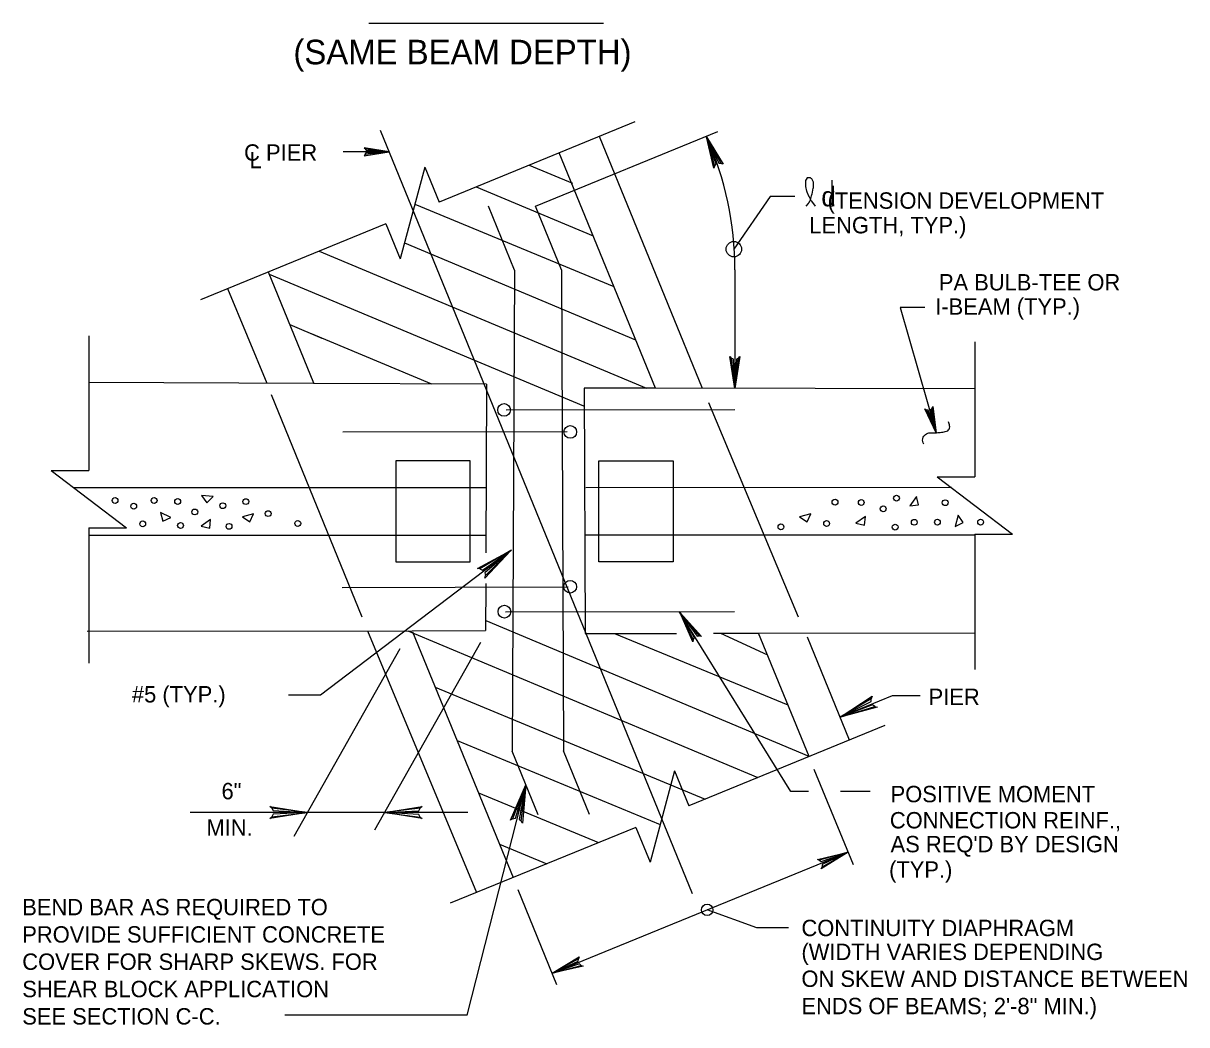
# Model space of a CAD drawing. Extents: x 639980 to 641204, y 298038 to 300414.
# Drawn here: x 640298.4 to 640511.2, y 299434.1 to 299617.3 of the extents above; entities that cross this region are included whole.
import ezdxf

# ---------------------------------------------------------------- set-up
doc = ezdxf.new("R2010")
doc.units = 0
for name, color, linetype in [('1', 7, 'Continuous'), ('2', 7, 'Continuous'), ('3', 7, 'Continuous')]:
    doc.layers.add(name, color=color, linetype=linetype)

msp = doc.modelspace()

# ---------------------------------------------------------------- linework, layer by layer
at = {"layer": '1'}
msp.add_spline([(640463.14, 299540.3), (640462.94, 299541.25), (640463.27, 299541.89), (640464.09, 299542.35), (640464.99, 299542.34), (640465.92, 299542.42), (640466.84, 299542.53), (640467.69, 299542.89), (640467.87, 299543.65), (640467.67, 299544.35)], degree=3, dxfattribs=at)
at = {"layer": '2'}
for p, q in [((640361.59, 299617.3), (640404.52, 299617.3)), ((640410.3, 299599.24), (640374.46, 299584.58)), ((640420.86, 299458.03), (640363.74, 299597.7)), ((640392.12, 299583.84), (640425.48, 299597.49)), ((640422.68, 299550.5), (640403.83, 299596.59)), ((640365.33, 299593.8), (640356.95, 299593.8)), ((640414.06, 299550.51), (640396.45, 299593.57)), ((640371.85, 299590.97), (640367.36, 299574.22)), ((640371.85, 299590.97), (640374.46, 299584.58)), ((640442.39, 299588.99), (640442.38, 299588.99)), ((640442.9, 299588.34), (640442.8, 299588.59)), ((640446.38, 299583.8), (640446.38, 299588.57)), ((640441.48, 299588.27), (640441.5, 299587.58)), ((640441.52, 299587.43), (640441.71, 299586.57)), ((640441.75, 299586.45), (640442.05, 299585.73)), ((640442.71, 299586.01), (640442.93, 299587.1)), ((640442.94, 299587.23), (640442.96, 299588.04)), ((640435.03, 299585.63), (640428.4, 299575.97)), ((640439.56, 299585.63), (640435.03, 299585.63)), ((640441.61, 299583.82), (640442.03, 299584.3)), ((640442.09, 299585.65), (640442.56, 299584.79)), ((640442.11, 299584.43), (640442.36, 299584.88)), ((640442.42, 299585.02), (640442.69, 299585.94)), ((640442.6, 299584.73), (640443.24, 299583.82)), ((640388.26, 299572.14), (640383.49, 299583.81)), ((640396.89, 299572.17), (640392.12, 299583.84)), ((640364.75, 299580.61), (640330.8, 299566.72)), ((640364.75, 299580.61), (640367.36, 299574.22)), ((640343.23, 299571.8), (640351.52, 299551.52)), ((640388.26, 299572.14), (640387.84, 299484.14)), ((640396.89, 299572.17), (640397.21, 299484.18)), ((640428.56, 299572.18), (640428.57, 299550.49)), ((640335.77, 299568.75), (640342.96, 299551.43)), ((640463.35, 299565.28), (640458.82, 299565.28)), ((640458.82, 299565.28), (640465.39, 299542.38)), ((640310.4, 299560.12), (640310.4, 299535.47)), ((640472.47, 299558.99), (640472.47, 299534.33)), ((640351.57, 299551.39), (640310.4, 299551.56)), ((640383.17, 299551.26), (640351.52, 299551.39)), ((640383.17, 299551.26), (640383.02, 299520.42)), ((640401.02, 299550.53), (640401.18, 299505.64)), ((640414.06, 299550.51), (640401.02, 299550.53)), ((640472.47, 299550.43), (640414.06, 299550.51)), ((640360.42, 299508.63), (640343.79, 299549.3)), ((640440.22, 299508.65), (640423.84, 299547.88)), ((640386.77, 299546.55), (640428.55, 299546.63)), ((640397.9, 299542.54), (640356.85, 299542.46)), ((640303.5, 299535.47), (640310.4, 299535.47)), ((640303.5, 299535.47), (640317.3, 299524.97)), ((640465.57, 299534.33), (640472.47, 299534.33)), ((640465.57, 299534.33), (640479.37, 299523.83)), ((640383.08, 299532.3), (640307.69, 299532.28)), ((640468.21, 299532.33), (640401.33, 299532.31)), ((640310.4, 299524.97), (640310.4, 299500.19)), ((640310.4, 299524.97), (640317.3, 299524.97)), ((640383.04, 299523.6), (640310.4, 299523.58)), ((640472.47, 299523.63), (640401.12, 299523.61)), ((640472.47, 299523.83), (640472.47, 299499.05)), ((640472.47, 299523.83), (640479.37, 299523.83)), ((640352.75, 299494.4), (640387.7, 299520.95)), ((640398.06, 299514.11), (640356.77, 299514.03)), ((640383, 299514.78), (640382.96, 299506.17)), ((640386.63, 299509.61), (640428.52, 299509.69)), ((640438.8, 299476.76), (640418.42, 299509.67)), ((640310.1, 299506.06), (640369.54, 299506.15)), ((640361.38, 299506.14), (640381.31, 299458.25)), ((640369.61, 299506.15), (640382.96, 299506.17)), ((640369.61, 299505.98), (640388.01, 299460.99)), ((640401.18, 299505.64), (640417.9, 299505.67)), ((640424.66, 299505.68), (640432.93, 299505.7)), ((640432.93, 299505.7), (640472.47, 299505.78)), ((640442.16, 299483.13), (640432.93, 299505.7)), ((640362.7, 299469.7), (640382.08, 299504.03)), ((640449.54, 299486.15), (640441.85, 299504.95)), ((640347.98, 299468.59), (640367.36, 299502.92)), ((640346.91, 299494.4), (640352.75, 299494.4)), ((640457.33, 299494.22), (640447.87, 299490.35)), ((640462.47, 299494.22), (640457.33, 299494.22)), ((640456.01, 299488.8), (640420.17, 299474.14)), ((640392.61, 299472.47), (640387.84, 299484.14)), ((640401.98, 299472.5), (640397.21, 299484.18)), ((640417.56, 299480.53), (640413.07, 299463.78)), ((640417.56, 299480.53), (640420.17, 299474.14)), ((640450.27, 299463.29), (640443.11, 299480.79)), ((640379.6, 299435.84), (640390.36, 299477.98)), ((640442.07, 299476.76), (640438.8, 299476.76)), ((640453.35, 299476.76), (640447.9, 299476.76)), ((640350.4, 299472.89), (640328.95, 299472.89)), ((640364.49, 299472.89), (640350.4, 299472.89)), ((640379.73, 299472.89), (640364.49, 299472.89)), ((640410.46, 299470.17), (640376.51, 299456.28)), ((640410.46, 299470.17), (640413.07, 299463.78)), ((640395.17, 299443.48), (640449.32, 299465.62)), ((640396.04, 299441.35), (640388.94, 299458.72)), ((640432.57, 299451.8), (640423.52, 299455.07)), ((640438.41, 299451.8), (640432.57, 299451.8)), ((640379.6, 299435.84), (640346.26, 299435.84))]:
    msp.add_line(p, q, dxfattribs=at)
for points in [[(640424.85, 299591.15), (640425.14, 299591.49), (640423.4, 299596.53), (640424.85, 299591.15), (640424.73, 299590.79), (640423.4, 299596.53), (640425.66, 299591.7), (640426.1, 299591.67), (640423.4, 299596.53), (640426.46, 299591.5), (640426.1, 299591.67)], [(640360.97, 299593.26), (640361.14, 299593.57), (640365.33, 299593.8), (640360.97, 299593.26), (640360.75, 299593.07), (640365.33, 299593.8), (640361.14, 299594.01), (640360.99, 299594.32), (640365.33, 299593.8), (640360.75, 299594.53), (640360.99, 299594.32)], [(640390.93, 299591.32), (640398.85, 299588.03)], [(640441.88, 299589.01), (640441.83, 299588.99), (640441.63, 299588.73)], [(640381.26, 299587.36), (640402.66, 299578.38)], [(640370.04, 299584.21), (640406.45, 299569.12)], [(640352.56, 299575.62), (640412.42, 299550.52)], [(640368.14, 299577.14), (640410.42, 299559.4)], [(640343.38, 299571.42), (640400.91, 299547.29)], [(640347.17, 299562.17), (640353.04, 299559.7)], [(640351.08, 299560.52), (640373.06, 299551.31)], [(640429.26, 299556.03), (640428.86, 299555.82), (640428.57, 299550.49), (640429.26, 299556.03), (640429.5, 299556.31), (640428.57, 299550.49), (640428.3, 299555.82), (640427.91, 299556.01), (640428.57, 299550.49), (640427.64, 299556.31), (640427.91, 299556.01)], [(640383, 299508.03), (640442.12, 299483.23)], [(640368.74, 299506.15), (640432.77, 299479.29)], [(640406.55, 299505.65), (640438.28, 299492.61)], [(640425.94, 299505.69), (640434.54, 299501.75)], [(640373.77, 299495.8), (640423.12, 299475.35)], [(640377.75, 299486.08), (640414.92, 299470.68)], [(640387.92, 299471.74), (640388.45, 299471.86), (640390.36, 299477.98), (640387.92, 299471.74), (640387.56, 299471.48), (640390.36, 299477.98), (640389.1, 299471.7), (640389.51, 299471.36), (640390.36, 299477.98), (640389.73, 299470.93), (640389.51, 299471.36)], [(640381.67, 299476.49), (640403.65, 299467.38)], [(640385.51, 299467.1), (640394.18, 299463.51)]]:
    msp.add_lwpolyline(points, dxfattribs=at)
for points in [[(640366.58, 299518.74), (640380.18, 299518.74), (640380.18, 299537.22), (640366.58, 299537.22)], [(640417.28, 299518.74), (640403.68, 299518.74), (640403.68, 299537.22), (640417.28, 299537.22)], [(640331.99, 299529.56), (640333.14, 299530.7), (640331.03, 299530.89)], [(640462.19, 299529.16), (640461.78, 299530.72), (640460.56, 299528.99)], [(640323.93, 299526.18), (640325.39, 299526.86), (640323.48, 299527.76)], [(640339.84, 299526.06), (640340.53, 299527.52), (640338.48, 299526.98)], [(640441.79, 299526.06), (640442.48, 299527.52), (640440.43, 299526.98)], [(640452.31, 299525.45), (640452.45, 299527.06), (640450.71, 299525.85)], [(640470.32, 299525.94), (640469.4, 299527.27), (640468.85, 299525.22)], [(640332.51, 299524.89), (640332.66, 299526.5), (640330.92, 299525.29)]]:
    msp.add_lwpolyline(points, close=True, dxfattribs=at)
for centre, radius in [((640428.4, 299575.97), 1.41), ((640386.36, 299546.55), 1.16), ((640398.46, 299542.53), 1.16), ((640458.15, 299530.41), 0.533), ((640315.2, 299529.98), 0.533), ((640318.61, 299528.93), 0.533), ((640322.34, 299529.98), 0.533), ((640326.65, 299529.8), 0.533), ((640334.9, 299529.03), 0.533), ((640339.12, 299529.77), 0.533), ((640446.9, 299529.67), 0.533), ((640451.7, 299529.62), 0.533), ((640455.72, 299528.46), 0.533), ((640467.06, 299529.58), 0.533), ((640329.78, 299527.88), 0.533), ((640343.2, 299527.58), 0.533), ((640320.26, 299525.7), 0.533), ((640327.18, 299525.4), 0.533), ((640336.05, 299525.25), 0.533), ((640348.62, 299525.78), 0.533), ((640437.01, 299525.15), 0.533), ((640445.37, 299525.76), 0.533), ((640457.91, 299525.11), 0.533), ((640461.4, 299525.99), 0.533), ((640465.63, 299526.02), 0.533), ((640473.54, 299526.03), 0.533), ((640398.45, 299514.19), 1.16), ((640386.42, 299509.64), 1.16), ((640423.52, 299455.07), 1.05)]:
    msp.add_circle(centre, radius, dxfattribs=at)
for centre, radius, start, end in [((640369.54, 299572.39), 59.03, 359.7921, 24.1399), ((640442.21, 299588.29), 0.729, 142.942, 181.1567), ((640442.12, 299588.31), 0.729, 68.3745, 108.4443), ((640442.13, 299588.31), 0.729, 22.4358, 68.3745), ((640442.23, 299588.06), 0.729, 358.8549, 22.4358), ((640442.23, 299587.6), 0.729, 181.1567, 192.772), ((640442.42, 299586.73), 0.729, 192.772, 202.4051), ((640442.21, 299587.25), 0.729, 348.6689, 358.8549), ((640441.47, 299584.77), 0.729, 319.6823, 331.4731), ((640442.72, 299586), 0.729, 202.4051, 209.0413), ((640441.72, 299585.23), 0.729, 331.4731, 343.3094), ((640443.2, 299585.15), 0.729, 209.0413, 214.8098), ((640441.99, 299586.15), 0.729, 343.3094, 348.6689)]:
    msp.add_arc(centre, radius, start, end, dxfattribs=at)
at = {"layer": '3'}
for points in [[(640464.66, 299546.89), (640464.4, 299546.64), (640465.39, 299542.38), (640464.66, 299546.89), (640464.79, 299547.17), (640465.39, 299542.38), (640463.96, 299546.51), (640463.6, 299546.57), (640465.39, 299542.38), (640463.32, 299546.74), (640463.6, 299546.57)], [(640381.94, 299517.49), (640382.43, 299517.26), (640387.62, 299520.84), (640381.94, 299517.49), (640381.51, 299517.51), (640387.62, 299520.84), (640382.83, 299516.74), (640382.94, 299516.23), (640387.62, 299520.84), (640382.85, 299515.77), (640382.94, 299516.23)], [(640420.97, 299504.47), (640421.19, 299504.86), (640418.6, 299509.42), (640420.97, 299504.47), (640420.92, 299504.11), (640418.6, 299509.42), (640421.66, 299505.16), (640422.09, 299505.21), (640418.6, 299509.42), (640422.46, 299505.1), (640422.09, 299505.21)], [(640454.18, 299492.26), (640453.76, 299492.59), (640447.87, 299490.35), (640454.18, 299492.26), (640454.6, 299492.14), (640447.87, 299490.35), (640453.49, 299493.2), (640453.5, 299493.72), (640447.87, 299490.35), (640453.7, 299494.15), (640453.5, 299493.72)], [(640343.86, 299473.71), (640344.11, 299473.23), (640350.4, 299472.89), (640343.86, 299473.71), (640343.53, 299473.99), (640350.4, 299472.89), (640344.11, 299472.57), (640343.89, 299472.1), (640350.4, 299472.89), (640343.53, 299471.79), (640343.89, 299472.1)], [(640371.03, 299472.06), (640370.79, 299472.54), (640364.49, 299472.89), (640371.03, 299472.06), (640371.37, 299471.78), (640364.49, 299472.89), (640370.79, 299473.2), (640371.01, 299473.66), (640364.49, 299472.89), (640371.37, 299473.98), (640371.01, 299473.66)], [(640444.02, 299464.18), (640444.36, 299463.9), (640449.32, 299465.62), (640444.02, 299464.18), (640443.67, 299464.3), (640449.32, 299465.62), (640444.57, 299463.39), (640444.54, 299462.95), (640449.32, 299465.62), (640444.37, 299462.6), (640444.54, 299462.95)], [(640400.47, 299444.92), (640400.13, 299445.2), (640395.17, 299443.48), (640400.47, 299444.92), (640400.82, 299444.8), (640395.17, 299443.48), (640399.92, 299445.71), (640399.95, 299446.14), (640395.17, 299443.48), (640400.12, 299446.5), (640399.95, 299446.14)]]:
    msp.add_lwpolyline(points, dxfattribs=at)

# ---------------------------------------------------------------- texts
at = {"layer": '2'}
for s, height, p in [('(SAME BEAM DEPTH)', 4.5, (640347.82, 299609.79)), ('d', 3.6, (640444.39, 299583.81)), ('   (TENSION DEVELOPMENT', 3, (640442.19, 299583.36)), ('LENGTH, TYP.)', 3, (640442.19, 299578.86))]:
    msp.add_text(s, height=height, dxfattribs=at).set_placement(p)
at = {"layer": '3'}
for s, height, p in [('C PIER', 2.999, (640338.8, 299592.15)), ('L', 3, (640339.81, 299590.76)), ('PA BULB-TEE OR', 2.9969, (640465.9, 299568.41)), ('I-BEAM (TYP.)', 2.9969, (640465.23, 299563.97)), ('#5 (TYP.)', 2.997, (640318.28, 299493.03)), ('PIER', 2.997, (640464.02, 299492.56)), ('6"', 2.997, (640334.67, 299475.31)), ('POSITIVE MOMENT', 2.9969, (640457.07, 299474.77)), ('MIN.', 2.997, (640331.91, 299468.64)), ('CONNECTION REINF.,', 2.9969, (640456.93, 299469.98)), ("AS REQ'D BY DESIGN", 2.9969, (640457.07, 299465.61)), ('(TYP.)', 2.997, (640456.79, 299460.96)), ('BEND BAR AS REQUIRED TO', 2.9969, (640298.22, 299454.09)), ('PROVIDE SUFFICIENT CONCRETE', 2.9969, (640298.22, 299449.09)), ('CONTINUITY DIAPHRAGM', 2.9969, (640440.76, 299450.27)), ('(WIDTH VARIES DEPENDING', 2.9969, (640440.76, 299445.9)), ('COVER FOR SHARP SKEWS. FOR', 2.9969, (640298.22, 299444.1)), ('ON SKEW AND DISTANCE BETWEEN', 2.9969, (640440.76, 299440.98)), ('SHEAR BLOCK APPLICATION', 2.9969, (640298.22, 299439.1)), ('ENDS OF BEAMS; 2\'-8" MIN.)', 2.9969, (640440.76, 299435.98)), ('SEE SECTION C-C.', 2.9969, (640298.22, 299434.1))]:
    msp.add_text(s, height=height, dxfattribs=at).set_placement(p)

doc.saveas('drawing.dxf')
